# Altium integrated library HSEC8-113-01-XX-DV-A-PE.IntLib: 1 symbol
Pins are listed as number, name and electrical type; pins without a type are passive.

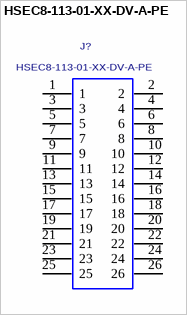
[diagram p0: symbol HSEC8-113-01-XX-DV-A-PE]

## HSEC8-113-01-XX-DV-A-PE
designator J?
0.8MM HIGH SPEED ASSEMBLY.; MANUFACTURER: SAMTEC
footprint HSEC8-113-01-XX-DV-A-PE
pins: 1, 2, 3, 4, 5, 6, 7, 8, 9, 10, 11, 12, 13, 14, 15, 16, 17, 18, 19, 20, 21, 22, 23, 24, 25, 26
